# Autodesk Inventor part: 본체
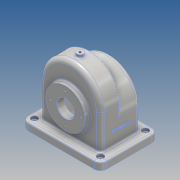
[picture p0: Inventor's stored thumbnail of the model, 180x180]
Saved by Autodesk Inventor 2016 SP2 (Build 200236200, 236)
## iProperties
Created: 2017-11
Part Number: 본체
Material: 알루미늄 6061
Document SubType Name: Modeling
Designer: Administrator
Density: 2.7 g/cm^3
Appearance: 알루미늄 - 평지
Author: Administrator
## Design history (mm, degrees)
sketch "스케치1"
  geometry: L1 (-63, 55)-(63, 55); L2 (75, 43)-(75, -43); L3 (63, -55)-(-63, -55); L4 (-75, -43)-(-75, 43); L5 (-75, 55)-(75, -55); L6 (75, 55)-(-75, -55); A1 r 12 centre (-63, 43) between (-63, 55) and (-75, 43); A2 r 12 centre (-63, -43) between (-75, -43) and (-63, -55); A3 r 12 centre (63, -43) between (63, -55) and (75, -43); A4 r 12 centre (63, 43) between (75, 43) and (63, 55); 1 further point
  constraints: 12 end point, 8 point on circle, 8 point on line, 8 tangent, 4 centre point, 3 equal radius, 2 midpoint, 2 parallel, 1 horizontal, 1 perpendicular
  dimensions: "d0" = 150 distance of L5.end L6.end; "d1" = 110 distance of L6.start L5.end; "d2" = 12 radius of A1
extrude "돌출1" new body sketch "스케치1" distance "d3" = 15; taper "d4" = 0 deg
sketch "스케치2"
  geometry: L1 (-63, 0)-(63, 0) reference; L2 (-58, 80)-(-58, 15); L3 (58, 80)-(58, 15); L4 (-63, 15)-(63, 15) reference; A1 r 58 centre (0, 80) between (58, 80) and (-58, 80); 2 further points
  constraints: 4 end point, 2 point on circle, 2 point on line, 2 tangent, 1 centre point, 1 midpoint, 1 perpendicular, 1 vertical, 1 vertical alignment
  dimensions: "d5" = 116 diameter of A1; "d6" = 80 distance from line of A1.centre L1
extrude "돌출2" join sketch "스케치2" distance "d7" = 38; taper "d8" = 0 deg
sketch "스케치3"
  geometry: L1 (-63, 0)-(63, 0) reference; L2 (-58, -15)-(-58, -57); L3 (-58, -80)-(-58, -15) reference; L4 (58, -15)-(58, -57); L5 (58, -15)-(-58, -15) reference; A1 r 58 centre (0, -80) between (-58, -80) and (58, -80) reference; A2 r 58 centre (0, -57) between (-58, -57) and (58, -57); 1 further point
  constraints: 4 end point, 2 point on circle, 2 point on line, 2 tangent, 1 centre point, 1 collinear, 1 vertical, 1 vertical alignment
  dimensions: "d9" = 116 diameter of A2; "d10" = 57 distance from line of A2.centre L1
extrude "돌출3" join sketch "스케치3" distance "d11" = 38; taper "d12" = 0 deg
sketch "스케치5"
  geometry: L1 (-63, -55)-(63, -55) reference; L2 (-41.963, -38)-(49.261, -38); C1 r 6 at (0, -19); 1 further point
  constraints: 2 end point, 1 centre point, 1 horizontal, 1 vertical alignment
  dimensions: "d14" = 12 diameter of C1; "d15" = 38 distance from line of L2 point (0, 0); "d16" = 19 distance from line of C1.centre L2
extrude "돌출4" join sketch "스케치5" distance "d17" = 144; taper "d18" = 0 deg
sketch "스케치7"
  geometry: L1 (-63, 0)-(63, 0) reference; C1 r 37.5 at (0, 65); 2 further points
  constraints: 1 centre point, 1 midpoint, 1 vertical alignment
  dimensions: "d20" = 75 diameter of C1; "d21" = 65 distance from line of C1.centre L1
extrude "돌출5" join sketch "스케치7" distance "d22" = 9; taper "d23" = 0 deg
sketch "스케치8"
  geometry: L1 (63, 0)-(-63, 0) reference; C1 r 31 at (0, -65); 2 further points
  constraints: 1 centre point, 1 midpoint, 1 vertical alignment
  dimensions: "d24" = 62 diameter of C1; "d25" = 65 distance from line of C1.centre L1
extrude "돌출6" join sketch "스케치8" distance "d26" = 10; taper "d27" = 0 deg
sketch "스케치9"
  geometry: C1 r 31 at (0, 0) reference; C2 r 16 at (0, 0); 1 further point
  constraints: 1 centre point, 1 coincident
  dimensions: "d28" = 32 diameter of C2
extrude "돌출7" cut sketch "스케치9" stored distance "d29" = 10; taper "d30" = 0 deg
node "작업 평면1"
sketch "스케치11"
  geometry: L1 (-63, 0)-(63, 0) reference; L2 (53, 0)-(53, 75); L3 (-53, 0)-(-53, 75); A1 r 53 centre (0, 75) between (53, 75) and (-53, 75); 2 further points
  constraints: 4 end point, 2 point on circle, 2 point on line, 2 tangent, 2 vertical, 1 centre point, 1 midpoint, 1 vertical alignment
  dimensions: "d34" = 106 diameter of A1; "d35" = 75 distance from line of A1.centre L1
extrude "돌출8" cut sketch "스케치11" distance "d36" = 28; taper "d37" = 0 deg
node "작업 평면2"
sketch "스케치12"
  geometry: L1 (-63, 0)-(63, 0) reference; L2 (53, 0)-(53, 52); L3 (-53, 0)-(-53, 52); A1 r 53 centre (0, 52) between (53, 52) and (-53, 52); 2 further points
  constraints: 4 end point, 2 point on circle, 2 point on line, 2 tangent, 2 vertical, 1 centre point, 1 midpoint, 1 vertical alignment
  dimensions: "d39" = 106 diameter of A1; "d40" = 52 distance from line of A1.centre L1
extrude "돌출9" cut sketch "스케치12" distance "d41" = 38; taper "d42" = 0 deg
sketch "스케치13"
  geometry: C1 r 16 at (0, 0) reference; 5 further points
  constraints: 2 horizontal alignment, 2 vertical alignment
  dimensions: "d43" = 58 distance of point (-29, 0) point (29, 0); "d44" = 58 distance of point (0, -29) point (0, 29); "d45" = 29 distance of point (0, -29) C1.centre; "d46" = 29 distance of C1.centre point (29, 0)
hole "구멍1" sketch "스케치13" at (0, 29), (29, 0), (0, -29), (-29, 0) diameter "d47" = 2.459; stored, may be unused: countersink angle "d51" = 90 deg, drill point angle "d53" = 0 deg; dims "d48" = 5, "d49" = 4, "d50" = 2, "d52" = 8
sketch "스케치14"
  geometry: C1 r 16 at (0, 0) reference; 5 further points
  constraints: 2 horizontal alignment, 2 vertical alignment
  dimensions: "d54" = 52 distance of point (26, 0) point (-26, 0); "d55" = 52 distance of point (0, 26) point (0, -26); "d56" = 26 distance of C1.centre point (-26, 0); "d57" = 26 distance of point (0, 26) C1.centre
hole "구멍2" sketch "스케치14" at (0, -26), (-26, 0), (0, 26), (26, 0) diameter "d58" = 2.459; stored, may be unused: countersink angle "d62" = 90 deg, drill point angle "d64" = 0 deg; dims "d59" = 5, "d60" = 4, "d61" = 2, "d63" = 8
sketch "스케치15"
  geometry: A1 r 12 centre (-63, -43) between (-75, -43) and (-63, -55) reference; A2 r 12 centre (63, 43) between (75, 43) and (63, 55) reference; A3 r 12 centre (-63, 43) between (-63, 55) and (-75, 43) reference; A4 r 12 centre (63, -43) between (63, -55) and (75, -43) reference; 5 further points
  constraints: 4 coincident
hole "구멍3" sketch "스케치15" at (-63, 43), (63, 43), (63, -43), (-63, -43) diameter "d65" = 5; stored, may be unused: countersink angle "d69" = 90 deg, drill point angle "d71" = 0 deg; dims "d66" = 5, "d67" = 12, "d68" = 5, "d70" = 8
sketch "스케치16"
  geometry: C1 r 6 at (0, 0) reference; 2 further points
  constraints: 1 coincident
hole "구멍4" sketch "스케치16" at (0, 0) diameter "d72" = 4.459; stored, may be unused: countersink angle "d76" = 90 deg, drill point angle "d78" = 0 deg; dims "d73" = 10, "d74" = 12, "d75" = 5, "d77" = 50
node "작업 평면3"
sketch "스케치17"
  geometry: L1 (-43, 0)-(43, 0) reference; L2 (-38, 15)-(-38, 80) reference; 2 further points
  constraints: 1 other
  dimensions: "d80" = 40 distance from line of point (0, 40) L1; "d81" = 38 distance from line of point (0, 40) L2
feature "엠보싱1" sketch "스케치17" dims "d0" = 150, "d1" = 110, "d2" = 12, "d5" = 116, "d6" = 80, "d82" = 0.5, "d83" = 0
fillet "모깎기1" dims "d84" = 8, "d85" = 3
fillet "모깎기2" dims "d86" = 3
chamfer "모따기1" distance "d87" = 1; stored, may be unused: second distance "d88" = 2, angle "d89" = 45 deg
node "솔리드1"
other parameters: "d33" = -5, "d38" = -5, "d79" = 75
